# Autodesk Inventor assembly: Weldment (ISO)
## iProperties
Length Units: 11269
Angle Units: 11283
Time Units: 11279
Mass Units: 11290
Length Display Precision: 3
Angle Display Precision: 2
Part Number: Weldment (ISO)
Document SubType Name: Weldment
Created: 2002-06
Designer: smithga
Part Number: protection meule
Created: 2005-01
Designer: LEGERET Philippe
Material: Aluminum soudé-6061
Control State: 0
Master: False
Shininess: 64.0
Angle Units: 11279
Time Units: 11290
Mass Units: 11283
Compacted: True
Density: 0.0
Volumn: 0.0
Area: 0.0
PropertySet Name: Model Information
Author: LEGERET Philippe
